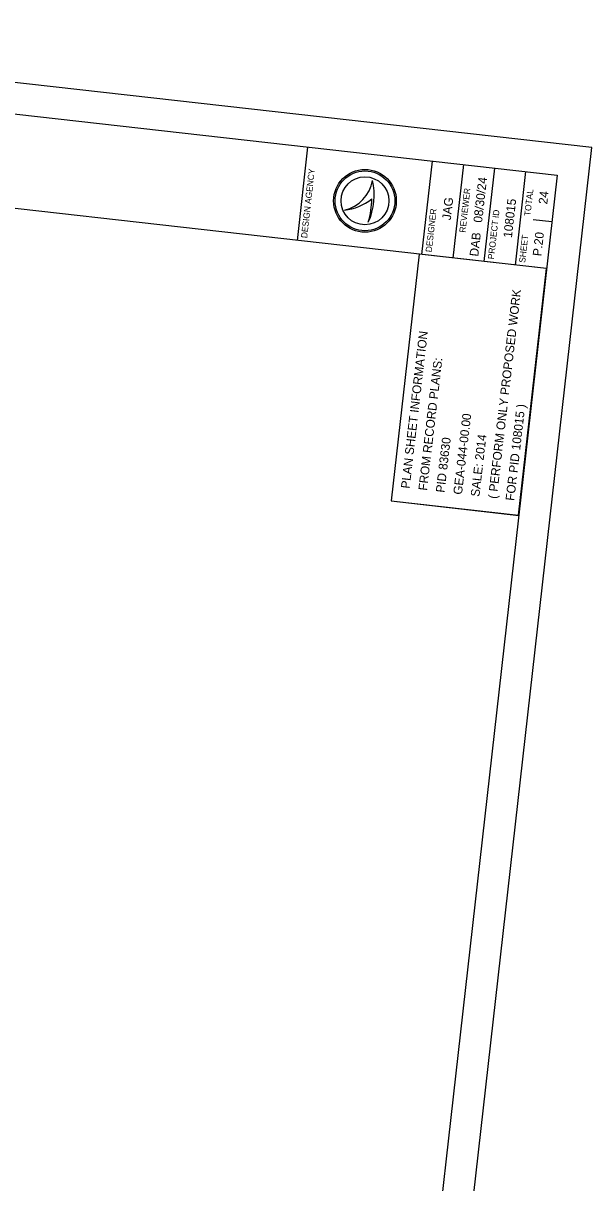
# Model space of a CAD drawing. Extents: x 2319604 to 2321967, y 627112 to 631396.
# Drawn here: x 2321165 to 2321618, y 629542 to 630466 of the extents above; entities that cross this region are included whole.
import ezdxf

# ---------------------------------------------------------------- set-up
doc = ezdxf.new("R2010")
doc.units = 0
for name, color, linetype in [('SC_Shading3', 7, 'Continuous'), ('SH_Border', 7, 'Continuous'), ('SH_Cut_Line', 7, 'Continuous'), ('SH_Data', 7, 'Continuous')]:
    doc.layers.add(name, color=color, linetype=linetype)

msp = doc.modelspace()

# ---------------------------------------------------------------- linework, layer by layer
at = {"layer": 'SC_Shading3'}
msp.add_lwpolyline([(2321560.08, 630074.03), (2321582.3, 630270.83), (2321480.6, 630282.31), (2321458.38, 630085.51)], close=True, dxfattribs=at)
at = {"layer": 'SH_Border'}
for p, q in [((2321582.29, 630270.76), (2320538.92, 630388.54)), ((2321383.55, 630293.2), (2321391.97, 630367.72)), ((2321482.92, 630281.98), (2321491.34, 630356.51)), ((2321507.77, 630279.17), (2321516.18, 630353.7)), ((2321532.61, 630276.37), (2321541.02, 630350.9)), ((2321557.45, 630273.57), (2321565.86, 630348.09))]:
    msp.add_line(p, q, dxfattribs=at)
msp.add_lwpolyline([(2320367.86, 628873.17), (2320547.33, 630463.07), (2321590.71, 630345.29), (2321411.23, 628755.39)], close=True, dxfattribs=at)
at = {"layer": 'SH_Cut_Line'}
msp.add_lwpolyline([(2321427.66, 628678.05), (2321618.35, 630367.33), (2320525.29, 630490.72), (2320334.6, 628801.44)], close=True, dxfattribs=at)
at = {"layer": 'SH_Data'}
for p, q in [((2321443.39, 630341.15), (2321443.39, 630341.15)), ((2321437.45, 630324.85), (2321437.45, 630324.85)), ((2321421.04, 630317.52), (2321421.04, 630317.52)), ((2321440.07, 630307.81), (2321440.07, 630307.81)), ((2321586.5, 630308.02), (2321571.59, 630309.71)), ((2321575.7, 630290.37), (2321575.7, 630290.37))]:
    msp.add_line(p, q, dxfattribs=at)
msp.add_lwpolyline([(2321559.9, 630074.12), (2321582.29, 630270.76), (2321480.6, 630282.31), (2321458.21, 630085.67)], close=True, dxfattribs=at)
for radius in [25, 23.84, 23.84, 19.11]:
    msp.add_circle((2321437.45, 630324.85), radius, dxfattribs=at)
for centre, radius, start, end in [((2321414.77, 630345.82), 28.99, 282.49138, 350.72518), ((2321394.16, 630329.2), 50.66, 335.01708, 13.64268), ((2321417.44, 630357.13), 39.78, 275.20159, 309.65411), ((2321379.52, 630326.26), 63.3, 343.05896, 0.22666), ((2321414.77, 630345.82), 28.99, 282.48511, 282.49138), ((2321417.44, 630357.13), 39.78, 275.19736, 275.20159), ((2321379.52, 630326.26), 63.3, 343.05583, 343.05896), ((2321394.16, 630329.2), 50.66, 335.01218, 335.01708)]:
    msp.add_arc(centre, radius, start, end, dxfattribs=at)

# ---------------------------------------------------------------- texts
for s, height, rotation, p in [('DESIGN AGENCY', 5, 83.55944, (2321391.29, 630294.84)), ('08/30/24', 7, 83.55944, (2321530.8, 630307.15)), ('REVIEWER', 5, 83.55944, (2321517.58, 630299.29)), ('TOTAL', 5, 83.55944, (2321569.39, 630312.47)), ('24', 7, 83.55944, (2321582.78, 630321.85)), ('JAG', 7, 83.55944, (2321505.87, 630309.18)), ('108015', 7, 83.55944, (2321554.6, 630295.08)), ('DESIGNER', 5, 83.55944, (2321490.66, 630283.62)), ('PROJECT ID', 5, 83.55944, (2321540.34, 630278.01)), ('DAB', 7, 83.55944, (2321527.75, 630280.18)), ('SHEET', 5, 83.55944, (2321565.18, 630275.21)), ('P.20', 7, 83.55944, (2321578.1, 630280.4)), ('( PERFORM ONLY PROPOSED WORK', 7, 83.34454, (2321542.54, 630087)), ('PLAN SHEET INFORMATION', 7, 83.34454, (2321473.01, 630095.11)), ('FROM RECORD PLANS:', 7, 83.34454, (2321486.92, 630093.49)), ('GEA-044-00.00', 7, 83.34454, (2321514.73, 630090.24)), ('FOR PID 108015 )', 7, 83.34454, (2321556.45, 630085.38)), ('PID 83630', 7, 83.34454, (2321500.83, 630091.87)), ('SALE: 2014', 7, 83.34454, (2321528.64, 630088.62))]:
    msp.add_text(s, height=height, rotation=rotation, dxfattribs=at).set_placement(p)

doc.saveas('drawing.dxf')
